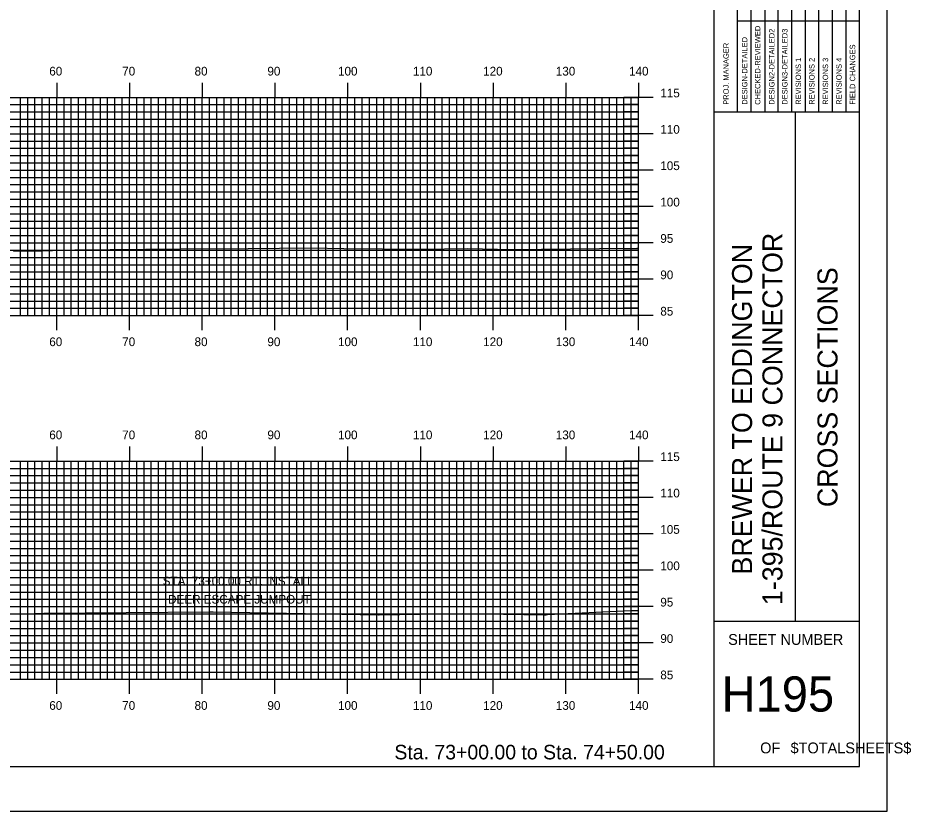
# Model space of a CAD drawing. Extents: x 1761004 to 1761347, y 442591 to 442811.
# Drawn here: x 1761224.4 to 1761347.2, y 442590.5 to 442699.6 of the extents above; entities that cross this region are included whole.
import ezdxf

# ---------------------------------------------------------------- set-up
doc = ezdxf.new("R2010")
doc.units = 0
for name, color, linetype in [('BORDER', 7, 'Continuous'), ('D_Text_Standard', 7, 'Continuous'), ('H_V ANNOTATION', 7, 'Continuous'), ('MAJOR', 7, 'Continuous'), ('MINOR', 7, 'Continuous'), ('PLOT BOUNDARY', 7, 'Continuous'), ('S_Roadway_Centerline', 7, 'Continuous')]:
    doc.layers.add(name, color=color, linetype=linetype)

msp = doc.modelspace()

# ---------------------------------------------------------------- linework, layer by layer
at = {"layer": 'BORDER'}
for p, q in [((1761320.13, 442596.67), (1761320.13, 442806.67)), ((1761320.13, 442686.67), (1761340.13, 442686.67)), ((1761331.31, 442616.67), (1761331.31, 442686.67)), ((1761320.13, 442616.67), (1761340.13, 442616.67))]:
    msp.add_line(p, q, dxfattribs=at)
msp.add_lwpolyline([(1761020.13, 442596.67), (1761340.13, 442596.67), (1761340.13, 442806.67), (1761020.13, 442806.67)], close=True, dxfattribs=at)
for points in [[(1761325.22, 442686.68), (1761325.22, 442721.67)], [(1761327.09, 442721.67), (1761327.09, 442686.68)], [(1761328.95, 442686.68), (1761328.95, 442721.67)], [(1761330.81, 442686.68), (1761330.81, 442721.67)], [(1761332.68, 442686.68), (1761332.68, 442721.67)], [(1761334.54, 442686.68), (1761334.54, 442721.67)], [(1761336.4, 442686.68), (1761336.4, 442721.67)], [(1761338.27, 442686.68), (1761338.27, 442721.67)], [(1761323.36, 442686.68), (1761323.36, 442720.26)], [(1761323.36, 442699.17), (1761340.13, 442699.17)]]:
    msp.add_lwpolyline(points, dxfattribs=at)
at = {"layer": 'MAJOR'}
for p, q in [((1761229.73, 442690.67), (1761229.73, 442688.67)), ((1761239.73, 442690.67), (1761239.73, 442688.67)), ((1761249.73, 442690.67), (1761249.73, 442688.67)), ((1761259.73, 442690.67), (1761259.73, 442688.67)), ((1761269.73, 442690.67), (1761269.73, 442688.67)), ((1761279.73, 442690.67), (1761279.73, 442688.67)), ((1761289.73, 442690.67), (1761289.73, 442688.67)), ((1761299.73, 442690.67), (1761299.73, 442688.67)), ((1761309.73, 442690.67), (1761309.73, 442688.67)), ((1761029.73, 442688.67), (1761309.73, 442688.67)), ((1761029.73, 442688.67), (1761309.73, 442688.67)), ((1761229.73, 442658.67), (1761229.73, 442688.67)), ((1761239.73, 442658.67), (1761239.73, 442688.67)), ((1761249.73, 442658.67), (1761249.73, 442688.67)), ((1761259.73, 442658.67), (1761259.73, 442688.67)), ((1761269.73, 442658.67), (1761269.73, 442688.67)), ((1761279.73, 442658.67), (1761279.73, 442688.67)), ((1761289.73, 442658.67), (1761289.73, 442688.67)), ((1761299.73, 442658.67), (1761299.73, 442688.67)), ((1761311.73, 442688.67), (1761307.72, 442688.67)), ((1761309.73, 442658.67), (1761309.73, 442688.67)), ((1761309.73, 442658.67), (1761309.73, 442688.67)), ((1761029.73, 442683.67), (1761309.73, 442683.67)), ((1761311.73, 442683.67), (1761307.72, 442683.67)), ((1761029.73, 442678.67), (1761309.73, 442678.67)), ((1761311.73, 442678.67), (1761307.72, 442678.67)), ((1761029.73, 442673.67), (1761309.73, 442673.67)), ((1761311.73, 442673.67), (1761307.72, 442673.67)), ((1761029.73, 442668.67), (1761309.73, 442668.67)), ((1761311.73, 442668.67), (1761307.72, 442668.67)), ((1761029.73, 442663.67), (1761309.73, 442663.67)), ((1761311.73, 442663.67), (1761307.72, 442663.67)), ((1761029.73, 442658.67), (1761309.73, 442658.67)), ((1761029.73, 442658.67), (1761309.73, 442658.67)), ((1761229.73, 442656.66), (1761229.73, 442658.67)), ((1761239.73, 442656.66), (1761239.73, 442658.67)), ((1761249.73, 442656.66), (1761249.73, 442658.67)), ((1761259.73, 442656.66), (1761259.73, 442658.67)), ((1761269.73, 442656.66), (1761269.73, 442658.67)), ((1761279.73, 442656.66), (1761279.73, 442658.67)), ((1761289.73, 442656.66), (1761289.73, 442658.67)), ((1761299.73, 442656.66), (1761299.73, 442658.67)), ((1761311.73, 442658.67), (1761307.72, 442658.67)), ((1761309.73, 442656.66), (1761309.73, 442658.67)), ((1761229.73, 442640.67), (1761229.73, 442638.67)), ((1761239.73, 442640.67), (1761239.73, 442638.67)), ((1761249.73, 442640.67), (1761249.73, 442638.67)), ((1761259.73, 442640.67), (1761259.73, 442638.67)), ((1761269.73, 442640.67), (1761269.73, 442638.67)), ((1761279.73, 442640.67), (1761279.73, 442638.67)), ((1761289.73, 442640.67), (1761289.73, 442638.67)), ((1761299.73, 442640.67), (1761299.73, 442638.67)), ((1761309.73, 442640.67), (1761309.73, 442638.67)), ((1761029.73, 442638.67), (1761309.73, 442638.67)), ((1761029.73, 442638.67), (1761309.73, 442638.67)), ((1761229.73, 442608.67), (1761229.73, 442638.67)), ((1761239.73, 442608.67), (1761239.73, 442638.67)), ((1761249.73, 442608.67), (1761249.73, 442638.67)), ((1761259.73, 442608.67), (1761259.73, 442638.67)), ((1761269.73, 442608.67), (1761269.73, 442638.67)), ((1761279.73, 442608.67), (1761279.73, 442638.67)), ((1761289.73, 442608.67), (1761289.73, 442638.67)), ((1761299.73, 442608.67), (1761299.73, 442638.67)), ((1761311.73, 442638.67), (1761307.72, 442638.67)), ((1761309.73, 442608.67), (1761309.73, 442638.67)), ((1761309.73, 442608.67), (1761309.73, 442638.67)), ((1761029.73, 442633.67), (1761309.73, 442633.67)), ((1761311.73, 442633.67), (1761307.72, 442633.67)), ((1761029.73, 442628.67), (1761309.73, 442628.67)), ((1761311.73, 442628.67), (1761307.72, 442628.67)), ((1761029.73, 442623.67), (1761309.73, 442623.67)), ((1761311.73, 442623.67), (1761307.72, 442623.67)), ((1761029.73, 442618.67), (1761309.73, 442618.67)), ((1761311.73, 442618.67), (1761307.72, 442618.67)), ((1761029.73, 442613.67), (1761309.73, 442613.67)), ((1761311.73, 442613.67), (1761307.72, 442613.67)), ((1761029.73, 442608.67), (1761309.73, 442608.67)), ((1761029.73, 442608.67), (1761309.73, 442608.67)), ((1761229.73, 442606.66), (1761229.73, 442608.67)), ((1761239.73, 442606.66), (1761239.73, 442608.67)), ((1761249.73, 442606.66), (1761249.73, 442608.67)), ((1761259.73, 442606.66), (1761259.73, 442608.67)), ((1761269.73, 442606.66), (1761269.73, 442608.67)), ((1761279.73, 442606.66), (1761279.73, 442608.67)), ((1761289.73, 442606.66), (1761289.73, 442608.67)), ((1761299.73, 442606.66), (1761299.73, 442608.67)), ((1761311.73, 442608.67), (1761307.72, 442608.67)), ((1761309.73, 442606.66), (1761309.73, 442608.67))]:
    msp.add_line(p, q, dxfattribs=at)
at = {"layer": 'MINOR'}
for p, q in [((1761224.73, 442658.67), (1761224.73, 442688.67)), ((1761225.73, 442658.67), (1761225.73, 442688.67)), ((1761226.73, 442658.67), (1761226.73, 442688.67)), ((1761227.73, 442658.67), (1761227.73, 442688.67)), ((1761228.73, 442658.67), (1761228.73, 442688.67)), ((1761230.73, 442658.67), (1761230.73, 442688.67)), ((1761231.73, 442658.67), (1761231.73, 442688.67)), ((1761232.73, 442658.67), (1761232.73, 442688.67)), ((1761233.73, 442658.67), (1761233.73, 442688.67)), ((1761234.73, 442658.67), (1761234.73, 442688.67)), ((1761235.73, 442658.67), (1761235.73, 442688.67)), ((1761236.73, 442658.67), (1761236.73, 442688.67)), ((1761237.73, 442658.67), (1761237.73, 442688.67)), ((1761238.73, 442658.67), (1761238.73, 442688.67)), ((1761240.73, 442658.67), (1761240.73, 442688.67)), ((1761241.73, 442658.67), (1761241.73, 442688.67)), ((1761242.73, 442658.67), (1761242.73, 442688.67)), ((1761243.73, 442658.67), (1761243.73, 442688.67)), ((1761244.73, 442658.67), (1761244.73, 442688.67)), ((1761245.73, 442658.67), (1761245.73, 442688.67)), ((1761246.73, 442658.67), (1761246.73, 442688.67)), ((1761247.73, 442658.67), (1761247.73, 442688.67)), ((1761248.73, 442658.67), (1761248.73, 442688.67)), ((1761250.73, 442658.67), (1761250.73, 442688.67)), ((1761251.73, 442658.67), (1761251.73, 442688.67)), ((1761252.73, 442658.67), (1761252.73, 442688.67)), ((1761253.73, 442658.67), (1761253.73, 442688.67)), ((1761254.73, 442658.67), (1761254.73, 442688.67)), ((1761255.73, 442658.67), (1761255.73, 442688.67)), ((1761256.73, 442658.67), (1761256.73, 442688.67)), ((1761257.73, 442658.67), (1761257.73, 442688.67)), ((1761258.73, 442658.67), (1761258.73, 442688.67)), ((1761260.73, 442658.67), (1761260.73, 442688.67)), ((1761261.73, 442658.67), (1761261.73, 442688.67)), ((1761262.73, 442658.67), (1761262.73, 442688.67)), ((1761263.73, 442658.67), (1761263.73, 442688.67)), ((1761264.73, 442658.67), (1761264.73, 442688.67)), ((1761265.73, 442658.67), (1761265.73, 442688.67)), ((1761266.73, 442658.67), (1761266.73, 442688.67)), ((1761267.73, 442658.67), (1761267.73, 442688.67)), ((1761268.73, 442658.67), (1761268.73, 442688.67)), ((1761270.73, 442658.67), (1761270.73, 442688.67)), ((1761271.73, 442658.67), (1761271.73, 442688.67)), ((1761272.73, 442658.67), (1761272.73, 442688.67)), ((1761273.73, 442658.67), (1761273.73, 442688.67)), ((1761274.73, 442658.67), (1761274.73, 442688.67)), ((1761275.73, 442658.67), (1761275.73, 442688.67)), ((1761276.73, 442658.67), (1761276.73, 442688.67)), ((1761277.73, 442658.67), (1761277.73, 442688.67)), ((1761278.73, 442658.67), (1761278.73, 442688.67)), ((1761280.73, 442658.67), (1761280.73, 442688.67)), ((1761281.73, 442658.67), (1761281.73, 442688.67)), ((1761282.73, 442658.67), (1761282.73, 442688.67)), ((1761283.73, 442658.67), (1761283.73, 442688.67)), ((1761284.73, 442658.67), (1761284.73, 442688.67)), ((1761285.73, 442658.67), (1761285.73, 442688.67)), ((1761286.73, 442658.67), (1761286.73, 442688.67)), ((1761287.73, 442658.67), (1761287.73, 442688.67)), ((1761288.73, 442658.67), (1761288.73, 442688.67)), ((1761290.73, 442658.67), (1761290.73, 442688.67)), ((1761291.73, 442658.67), (1761291.73, 442688.67)), ((1761292.73, 442658.67), (1761292.73, 442688.67)), ((1761293.73, 442658.67), (1761293.73, 442688.67)), ((1761294.73, 442658.67), (1761294.73, 442688.67)), ((1761295.73, 442658.67), (1761295.73, 442688.67)), ((1761296.73, 442658.67), (1761296.73, 442688.67)), ((1761297.73, 442658.67), (1761297.73, 442688.67)), ((1761298.73, 442658.67), (1761298.73, 442688.67)), ((1761300.73, 442658.67), (1761300.73, 442688.67)), ((1761301.73, 442658.67), (1761301.73, 442688.67)), ((1761302.73, 442658.67), (1761302.73, 442688.67)), ((1761303.73, 442658.67), (1761303.73, 442688.67)), ((1761304.73, 442658.67), (1761304.73, 442688.67)), ((1761305.73, 442658.67), (1761305.73, 442688.67)), ((1761306.73, 442658.67), (1761306.73, 442688.67)), ((1761307.73, 442658.67), (1761307.73, 442688.67)), ((1761308.73, 442658.67), (1761308.73, 442688.67)), ((1761029.73, 442687.67), (1761309.73, 442687.67)), ((1761029.73, 442686.67), (1761309.73, 442686.67)), ((1761309.73, 442687.67), (1761307.72, 442687.67)), ((1761309.73, 442686.67), (1761307.72, 442686.67)), ((1761029.73, 442685.67), (1761309.73, 442685.67)), ((1761309.73, 442685.67), (1761307.72, 442685.67)), ((1761029.73, 442684.67), (1761309.73, 442684.67)), ((1761309.73, 442684.67), (1761307.72, 442684.67)), ((1761029.73, 442682.67), (1761309.73, 442682.67)), ((1761029.73, 442681.67), (1761309.73, 442681.67)), ((1761309.73, 442682.67), (1761307.72, 442682.67)), ((1761309.73, 442681.67), (1761307.72, 442681.67)), ((1761029.73, 442680.67), (1761309.73, 442680.67)), ((1761309.73, 442680.67), (1761307.72, 442680.67)), ((1761029.73, 442679.67), (1761309.73, 442679.67)), ((1761309.73, 442679.67), (1761307.72, 442679.67)), ((1761029.73, 442677.67), (1761309.73, 442677.67)), ((1761309.73, 442677.67), (1761307.72, 442677.67)), ((1761029.73, 442676.67), (1761309.73, 442676.67)), ((1761029.73, 442675.67), (1761309.73, 442675.67)), ((1761309.73, 442676.67), (1761307.72, 442676.67)), ((1761309.73, 442675.67), (1761307.72, 442675.67)), ((1761029.73, 442674.67), (1761309.73, 442674.67)), ((1761309.73, 442674.67), (1761307.72, 442674.67)), ((1761029.73, 442672.67), (1761309.73, 442672.67)), ((1761309.73, 442672.67), (1761307.72, 442672.67)), ((1761029.73, 442671.67), (1761309.73, 442671.67)), ((1761029.73, 442670.67), (1761309.73, 442670.67)), ((1761309.73, 442671.67), (1761307.72, 442671.67)), ((1761309.73, 442670.67), (1761307.72, 442670.67)), ((1761029.73, 442669.67), (1761309.73, 442669.67)), ((1761309.73, 442669.67), (1761307.72, 442669.67)), ((1761029.73, 442667.67), (1761309.73, 442667.67)), ((1761309.73, 442667.67), (1761307.72, 442667.67)), ((1761029.73, 442666.67), (1761309.73, 442666.67)), ((1761029.73, 442665.67), (1761309.73, 442665.67)), ((1761309.73, 442666.67), (1761307.72, 442666.67)), ((1761309.73, 442665.67), (1761307.72, 442665.67)), ((1761029.73, 442664.67), (1761309.73, 442664.67)), ((1761309.73, 442664.67), (1761307.72, 442664.67)), ((1761029.73, 442662.67), (1761309.73, 442662.67)), ((1761309.73, 442662.67), (1761307.72, 442662.67)), ((1761029.73, 442661.67), (1761309.73, 442661.67)), ((1761309.73, 442661.67), (1761307.72, 442661.67)), ((1761029.73, 442660.67), (1761309.73, 442660.67)), ((1761029.73, 442659.67), (1761309.73, 442659.67)), ((1761309.73, 442660.67), (1761307.72, 442660.67)), ((1761309.73, 442659.67), (1761307.72, 442659.67)), ((1761224.73, 442608.67), (1761224.73, 442638.67)), ((1761225.73, 442608.67), (1761225.73, 442638.67)), ((1761226.73, 442608.67), (1761226.73, 442638.67)), ((1761227.73, 442608.67), (1761227.73, 442638.67)), ((1761228.73, 442608.67), (1761228.73, 442638.67)), ((1761230.73, 442608.67), (1761230.73, 442638.67)), ((1761231.73, 442608.67), (1761231.73, 442638.67)), ((1761232.73, 442608.67), (1761232.73, 442638.67)), ((1761233.73, 442608.67), (1761233.73, 442638.67)), ((1761234.73, 442608.67), (1761234.73, 442638.67)), ((1761235.73, 442608.67), (1761235.73, 442638.67)), ((1761236.73, 442608.67), (1761236.73, 442638.67)), ((1761237.73, 442608.67), (1761237.73, 442638.67)), ((1761238.73, 442608.67), (1761238.73, 442638.67)), ((1761240.73, 442608.67), (1761240.73, 442638.67)), ((1761241.73, 442608.67), (1761241.73, 442638.67)), ((1761242.73, 442608.67), (1761242.73, 442638.67)), ((1761243.73, 442608.67), (1761243.73, 442638.67)), ((1761244.73, 442608.67), (1761244.73, 442638.67)), ((1761245.73, 442608.67), (1761245.73, 442638.67)), ((1761246.73, 442608.67), (1761246.73, 442638.67)), ((1761247.73, 442608.67), (1761247.73, 442638.67)), ((1761248.73, 442608.67), (1761248.73, 442638.67)), ((1761250.73, 442608.67), (1761250.73, 442638.67)), ((1761251.73, 442608.67), (1761251.73, 442638.67)), ((1761252.73, 442608.67), (1761252.73, 442638.67)), ((1761253.73, 442608.67), (1761253.73, 442638.67)), ((1761254.73, 442608.67), (1761254.73, 442638.67)), ((1761255.73, 442608.67), (1761255.73, 442638.67)), ((1761256.73, 442608.67), (1761256.73, 442638.67)), ((1761257.73, 442608.67), (1761257.73, 442638.67)), ((1761258.73, 442608.67), (1761258.73, 442638.67)), ((1761260.73, 442608.67), (1761260.73, 442638.67)), ((1761261.73, 442608.67), (1761261.73, 442638.67)), ((1761262.73, 442608.67), (1761262.73, 442638.67)), ((1761263.73, 442608.67), (1761263.73, 442638.67)), ((1761264.73, 442608.67), (1761264.73, 442638.67)), ((1761265.73, 442608.67), (1761265.73, 442638.67)), ((1761266.73, 442608.67), (1761266.73, 442638.67)), ((1761267.73, 442608.67), (1761267.73, 442638.67)), ((1761268.73, 442608.67), (1761268.73, 442638.67)), ((1761270.73, 442608.67), (1761270.73, 442638.67)), ((1761271.73, 442608.67), (1761271.73, 442638.67)), ((1761272.73, 442608.67), (1761272.73, 442638.67)), ((1761273.73, 442608.67), (1761273.73, 442638.67)), ((1761274.73, 442608.67), (1761274.73, 442638.67)), ((1761275.73, 442608.67), (1761275.73, 442638.67)), ((1761276.73, 442608.67), (1761276.73, 442638.67)), ((1761277.73, 442608.67), (1761277.73, 442638.67)), ((1761278.73, 442608.67), (1761278.73, 442638.67)), ((1761280.73, 442608.67), (1761280.73, 442638.67)), ((1761281.73, 442608.67), (1761281.73, 442638.67)), ((1761282.73, 442608.67), (1761282.73, 442638.67)), ((1761283.73, 442608.67), (1761283.73, 442638.67)), ((1761284.73, 442608.67), (1761284.73, 442638.67)), ((1761285.73, 442608.67), (1761285.73, 442638.67)), ((1761286.73, 442608.67), (1761286.73, 442638.67)), ((1761287.73, 442608.67), (1761287.73, 442638.67)), ((1761288.73, 442608.67), (1761288.73, 442638.67)), ((1761290.73, 442608.67), (1761290.73, 442638.67)), ((1761291.73, 442608.67), (1761291.73, 442638.67)), ((1761292.73, 442608.67), (1761292.73, 442638.67)), ((1761293.73, 442608.67), (1761293.73, 442638.67)), ((1761294.73, 442608.67), (1761294.73, 442638.67)), ((1761295.73, 442608.67), (1761295.73, 442638.67)), ((1761296.73, 442608.67), (1761296.73, 442638.67)), ((1761297.73, 442608.67), (1761297.73, 442638.67)), ((1761298.73, 442608.67), (1761298.73, 442638.67)), ((1761300.73, 442608.67), (1761300.73, 442638.67)), ((1761301.73, 442608.67), (1761301.73, 442638.67)), ((1761302.73, 442608.67), (1761302.73, 442638.67)), ((1761303.73, 442608.67), (1761303.73, 442638.67)), ((1761304.73, 442608.67), (1761304.73, 442638.67)), ((1761305.73, 442608.67), (1761305.73, 442638.67)), ((1761306.73, 442608.67), (1761306.73, 442638.67)), ((1761307.73, 442608.67), (1761307.73, 442638.67)), ((1761308.73, 442608.67), (1761308.73, 442638.67)), ((1761029.73, 442637.67), (1761309.73, 442637.67)), ((1761309.73, 442637.67), (1761307.72, 442637.67)), ((1761029.73, 442636.67), (1761309.73, 442636.67)), ((1761309.73, 442636.67), (1761307.72, 442636.67)), ((1761029.73, 442635.67), (1761309.73, 442635.67)), ((1761309.73, 442635.67), (1761307.72, 442635.67)), ((1761029.73, 442634.67), (1761309.73, 442634.67)), ((1761309.73, 442634.67), (1761307.72, 442634.67)), ((1761029.73, 442632.67), (1761309.73, 442632.67)), ((1761309.73, 442632.67), (1761307.72, 442632.67)), ((1761029.73, 442631.67), (1761309.73, 442631.67)), ((1761309.73, 442631.67), (1761307.72, 442631.67)), ((1761029.73, 442630.67), (1761309.73, 442630.67)), ((1761309.73, 442630.67), (1761307.72, 442630.67)), ((1761029.73, 442629.67), (1761309.73, 442629.67)), ((1761309.73, 442629.67), (1761307.72, 442629.67)), ((1761029.73, 442627.67), (1761309.73, 442627.67)), ((1761309.73, 442627.67), (1761307.72, 442627.67)), ((1761029.73, 442626.67), (1761309.73, 442626.67)), ((1761309.73, 442626.67), (1761307.72, 442626.67)), ((1761029.73, 442625.67), (1761309.73, 442625.67)), ((1761309.73, 442625.67), (1761307.72, 442625.67)), ((1761029.73, 442624.67), (1761309.73, 442624.67)), ((1761309.73, 442624.67), (1761307.72, 442624.67)), ((1761029.73, 442622.67), (1761309.73, 442622.67)), ((1761309.73, 442622.67), (1761307.72, 442622.67)), ((1761029.73, 442621.67), (1761309.73, 442621.67)), ((1761309.73, 442621.67), (1761307.72, 442621.67)), ((1761029.73, 442620.67), (1761309.73, 442620.67)), ((1761309.73, 442620.67), (1761307.72, 442620.67)), ((1761029.73, 442619.67), (1761309.73, 442619.67)), ((1761309.73, 442619.67), (1761307.72, 442619.67)), ((1761029.73, 442617.67), (1761309.73, 442617.67)), ((1761029.73, 442616.67), (1761309.73, 442616.67)), ((1761309.73, 442617.67), (1761307.72, 442617.67)), ((1761309.73, 442616.67), (1761307.72, 442616.67)), ((1761029.73, 442615.67), (1761309.73, 442615.67)), ((1761309.73, 442615.67), (1761307.72, 442615.67)), ((1761029.73, 442614.67), (1761309.73, 442614.67)), ((1761309.73, 442614.67), (1761307.72, 442614.67)), ((1761029.73, 442612.67), (1761309.73, 442612.67)), ((1761029.73, 442611.67), (1761309.73, 442611.67)), ((1761309.73, 442612.67), (1761307.72, 442612.67)), ((1761309.73, 442611.67), (1761307.72, 442611.67)), ((1761029.73, 442610.67), (1761309.73, 442610.67)), ((1761309.73, 442610.67), (1761307.72, 442610.67)), ((1761029.73, 442609.67), (1761309.73, 442609.67)), ((1761309.73, 442609.67), (1761307.72, 442609.67))]:
    msp.add_line(p, q, dxfattribs=at)
at = {"layer": 'PLOT BOUNDARY'}
msp.add_lwpolyline([(1761003.94, 442590.55), (1761343.94, 442590.55), (1761343.94, 442810.55), (1761003.94, 442810.55)], close=True, dxfattribs=at)
at = {"layer": 'S_Roadway_Centerline'}
for points in [[(1761223.79, 442667.52), (1761227.64, 442667.57), (1761232.2, 442667.7), (1761246.81, 442667.85), (1761256.04, 442667.9), (1761264.69, 442667.99), (1761269.19, 442667.88), (1761279.84, 442667.82), (1761286.21, 442667.88), (1761292.39, 442667.74), (1761304.36, 442667.87), (1761309.51, 442667.94), (1761309.73, 442667.93)], [(1761216.23, 442617.46), (1761226.62, 442617.73), (1761227.93, 442617.75), (1761239.29, 442617.83), (1761250.68, 442617.94), (1761251.24, 442617.94), (1761273.96, 442617.53), (1761274.02, 442617.53), (1761274.07, 442617.53), (1761285.48, 442617.73), (1761296.82, 442617.55), (1761297.01, 442617.55), (1761297.23, 442617.56), (1761308.62, 442618.13), (1761309.73, 442618.14)]]:
    msp.add_lwpolyline(points, dxfattribs=at)

# ---------------------------------------------------------------- texts
at = {"layer": 'BORDER'}
for s, height, p in [('CHECKED-REVIEWED', 0.7455, (1761326.49, 442687.65)), ('DESIGN2-DETAILED2', 0.7455, (1761328.43, 442687.65)), ('DESIGN3-DETAILED3', 0.7455, (1761330.22, 442687.65)), ('DESIGN-DETAILED', 0.7455, (1761324.7, 442687.65)), ('PROJ. MANAGER', 0.7455, (1761322.14, 442687.65)), ('FIELD CHANGES', 0.7455, (1761339.53, 442687.65)), ('REVISIONS 1', 0.7455, (1761332.08, 442687.65)), ('REVISIONS 2', 0.7455, (1761333.94, 442687.65)), ('REVISIONS 3', 0.7455, (1761335.81, 442687.65)), ('REVISIONS 4', 0.7455, (1761337.67, 442687.65)), ('1-395/ROUTE 9 CONNECTOR', 2.7557, (1761329.53, 442618.87)), ('BREWER TO EDDINGTON', 2.7557, (1761325.35, 442623.07)), ('CROSS SECTIONS', 2.7557, (1761337.1, 442632.34))]:
    msp.add_text(s, height=height, rotation=90, dxfattribs=at).set_placement(p)
for s, height, p in [('SHEET NUMBER', 1.4905, (1761322.06, 442613.4)), ('H195', 4.839, (1761321.16, 442604.23)), ('OF', 1.491, (1761326.46, 442598.49)), ('$TOTALSHEETS$', 1.4905, (1761330.64, 442598.49))]:
    msp.add_text(s, height=height, dxfattribs=at).set_placement(p)
at = {"layer": 'D_Text_Standard'}
for s, p in [('STA. 73+00.00 RT. INSTALL ', (1761244.3, 442621.57)), ('DEER ESCAPE JUMPOUT', (1761245.04, 442619.07))]:
    msp.add_text(s, height=1.2, dxfattribs=at).set_placement(p)
at = {"layer": 'H_V ANNOTATION'}
for s, height, p in [('60', 1.2, (1761228.7, 442691.67)), ('70', 1.2, (1761238.73, 442691.67)), ('80', 1.2, (1761248.68, 442691.67)), ('90', 1.2, (1761258.7, 442691.67)), ('100', 1.2, (1761268.41, 442691.67)), ('110', 1.2, (1761278.71, 442691.67)), ('120', 1.2, (1761288.37, 442691.67)), ('130', 1.2, (1761298.36, 442691.67)), ('140', 1.2, (1761308.43, 442691.67)), ('115', 1.2, (1761312.73, 442688.67)), ('110', 1.2, (1761312.73, 442683.67)), ('105', 1.2, (1761312.73, 442678.67)), ('100', 1.2, (1761312.73, 442673.67)), ('95', 1.2, (1761312.73, 442668.67)), ('90', 1.2, (1761312.73, 442663.67)), ('85', 1.2, (1761312.73, 442658.67)), ('60', 1.2, (1761228.7, 442654.47)), ('70', 1.2, (1761238.73, 442654.47)), ('80', 1.2, (1761248.68, 442654.47)), ('90', 1.2, (1761258.7, 442654.47)), ('100', 1.2, (1761268.41, 442654.47)), ('110', 1.2, (1761278.71, 442654.47)), ('120', 1.2, (1761288.37, 442654.47)), ('130', 1.2, (1761298.36, 442654.47)), ('140', 1.2, (1761308.43, 442654.47)), ('60', 1.2, (1761228.7, 442641.67)), ('70', 1.2, (1761238.73, 442641.67)), ('80', 1.2, (1761248.68, 442641.67)), ('90', 1.2, (1761258.7, 442641.67)), ('100', 1.2, (1761268.41, 442641.67)), ('110', 1.2, (1761278.71, 442641.67)), ('120', 1.2, (1761288.37, 442641.67)), ('130', 1.2, (1761298.36, 442641.67)), ('140', 1.2, (1761308.43, 442641.67)), ('115', 1.2, (1761312.73, 442638.67)), ('110', 1.2, (1761312.73, 442633.67)), ('105', 1.2, (1761312.73, 442628.67)), ('100', 1.2, (1761312.73, 442623.67)), ('95', 1.2, (1761312.73, 442618.67)), ('90', 1.2, (1761312.73, 442613.67)), ('85', 1.2, (1761312.73, 442608.67)), ('60', 1.2, (1761228.7, 442604.47)), ('70', 1.2, (1761238.73, 442604.47)), ('80', 1.2, (1761248.68, 442604.47)), ('90', 1.2, (1761258.7, 442604.47)), ('100', 1.2, (1761268.41, 442604.47)), ('110', 1.2, (1761278.71, 442604.47)), ('120', 1.2, (1761288.37, 442604.47)), ('130', 1.2, (1761298.36, 442604.47)), ('140', 1.2, (1761308.43, 442604.47)), ('Sta. 73+00.00 to Sta. 74+50.00', 2.0004, (1761276.16, 442597.66))]:
    msp.add_text(s, height=height, dxfattribs=at).set_placement(p)

doc.saveas('drawing.dxf')
